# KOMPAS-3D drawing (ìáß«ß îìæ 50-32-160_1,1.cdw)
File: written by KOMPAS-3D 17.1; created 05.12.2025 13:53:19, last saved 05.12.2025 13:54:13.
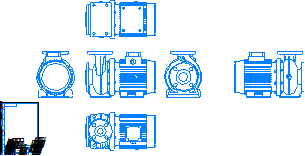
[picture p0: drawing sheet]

Sheet 1: A4, portrait

Title block, sheet 1: name: Насос МНС / 50-32-160_1,1; material: Сталь 10  ГОСТ 1050-88; mass: 75,61; sheets: 1; sheet format: A4

Views: Проекционный вид 2, Проекционный вид 3, Проекционный вид 4, Проекционный вид 5, Проекционный вид 6
Referenced files in \\adlc.lan\data\АДЛ_ПКД\3D-модели\ADL production\Насосы ГРАНПАМП\Насосы ГРАНПАМП серии МНС\KOMPAS 3D\: Насос МНС 50-32-160_1,1.m3d
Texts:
  Andrey
  АДЛ
Dimensions and other numbers on the sheet: 1:1; 1; 50-32-160_1,1; 75,61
